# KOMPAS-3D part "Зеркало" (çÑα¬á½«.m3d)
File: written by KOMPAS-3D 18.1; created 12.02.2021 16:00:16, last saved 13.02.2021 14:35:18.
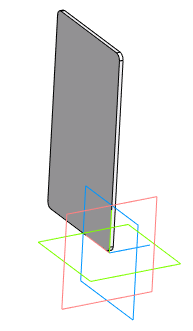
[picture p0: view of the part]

Document properties: Полное имя файла: C:\GoogleDrive\НИР\ИКИ\Компас\Зеркало.m3d

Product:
- Part/product: Зеркало
    Материал: Стекло БК10  ГОСТ 3514-94 (density 3120 kg/m3)
    Масса: 0.0382404
  - Body: Тело 1
      Масса: 0.0962874

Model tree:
1. Операция без истории:1  (labels: Стекло БК10  ГОСТ 3514-94)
